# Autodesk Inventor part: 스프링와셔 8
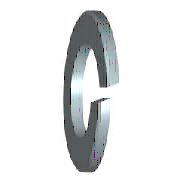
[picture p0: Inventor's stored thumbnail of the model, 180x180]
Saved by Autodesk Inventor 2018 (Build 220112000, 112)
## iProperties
IsCustomPart: 1
Created: 2012-02
Part Number: 스프링와셔 8
Material: 강철, 연강
Description: 스프링 잠금 와셔
Document SubType Name: Modeling
Standard: KS B 1324
Designer: mduedu
Standards Organization: KS
Language: ko-KR
Size Designation: 번호 3 - 8
Categories: <MemberInstance><Categories><Category DisplayName="조임쇠" InternalName="e4da775c-781d-43d5-af7c-5136215cf5a6" Mnemonic="FSTN"><Category DisplayName="와셔" InternalN
Density: 7.86 g/cm^3
Mass: 2.27751 g
Surface Area: 4.25113 cm^2
Volume: 0.289759 cm^3
Appearance: 파란색 - 벽 페인트 - 광택
Author: mduedu
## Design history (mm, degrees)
sketch "스케치1"
  geometry: C1 r 7.4 at (0, 0); C2 r 4.1 at (0, 0); 1 further point
  constraints: 2 centre point, 2 coincident
  dimensions: "d0" = 8.2 diameter of C2 (= SD1); "d1" = 14.8 diameter of C1 (= SD2)
extrude "본체" new body sketch "스케치1" distance "d2" = 2.5 (= SD); taper "d3" = 0 deg
sketch "스케치2"
  geometry: L1 (0, -4.1)-(0, 4.1) reference; L2 (2.5, 7.4)-(2.5, -7.4) reference; L3 (-1.2, 0)-(7.2, 0) reference; L4 (0, -0.5)-(2.5, 0.41); L5 (0, 0.5)-(2.5, 1.41)
  constraints: 4 end point, 4 point on line, 1 parallel
  dimensions: "d4" = 0.5 distance from line of L3 L4.start (= 0.2 x SD); "d5" = 0.5 distance from line of L3 L5.start (= 0.2 x SD); "d6" = 70 deg angle of L2 L4 (= FAWI)
extrude "절단부" cut sketch "스케치2" stored distance "d7" = 2.5 (= SD); taper "d8" = 0 deg
workaxis "Work Axis1"
workplane "Work Plane1"
body "Solid1"
other parameters: "SD1" = 8.2 [user parameter; used in 1 equation term], "SD2" = 14.8 [user parameter; used in 1 equation term], "SD" = 2.5 [user parameter; used in 4 equation terms], "FAWI" = 70 deg [user parameter; used in 1 equation term], "d9" = 0, "d10" = 0, "d11" = 0, "d12" = 0, "SDI" = 3.3 [user parameter], "NND" = 8 [user parameter]
